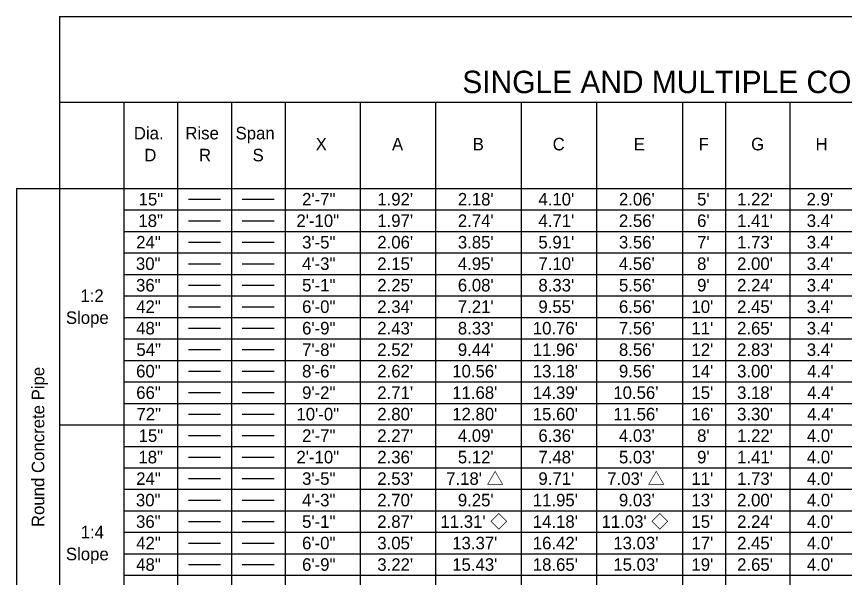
# Model space of a CAD drawing. Extents: x 1.7 to 14.6, y 0 to 8.4.
# Drawn here: x 1.7 to 6.325, y 5.298 to 8.43 of the extents above; entities that cross this region are included whole.
import ezdxf

# ---------------------------------------------------------------- set-up
doc = ezdxf.new("R2010")
doc.units = 0
doc.layers.add('Table', color=7, linetype='Continuous')

msp = doc.modelspace()

# ---------------------------------------------------------------- linework, layer by layer
at = {"layer": 'Table'}
for p, q in [((1.94, 8.43), (13.46, 8.43)), ((2.66, 7.41), (2.84, 7.41)), ((2.96, 7.41), (3.14, 7.41)), ((2.66, 7.29), (2.84, 7.29)), ((2.96, 7.29), (3.14, 7.29)), ((2.66, 7.17), (2.84, 7.17)), ((2.96, 7.17), (3.14, 7.17)), ((2.66, 7.05), (2.84, 7.05)), ((2.96, 7.05), (3.14, 7.05)), ((2.66, 6.93), (2.84, 6.93)), ((2.96, 6.93), (3.14, 6.93)), ((2.66, 6.81), (2.84, 6.81)), ((2.96, 6.81), (3.14, 6.81)), ((2.66, 6.69), (2.84, 6.69)), ((2.96, 6.69), (3.14, 6.69)), ((2.66, 6.57), (2.84, 6.57)), ((2.96, 6.57), (3.14, 6.57)), ((2.66, 6.45), (2.84, 6.45)), ((2.96, 6.45), (3.14, 6.45)), ((2.66, 6.33), (2.84, 6.33)), ((2.96, 6.33), (3.14, 6.33)), ((2.66, 6.21), (2.84, 6.21)), ((2.96, 6.21), (3.14, 6.21)), ((2.66, 6.09), (2.84, 6.09)), ((2.96, 6.09), (3.14, 6.09)), ((2.66, 5.97), (2.84, 5.97)), ((2.96, 5.97), (3.14, 5.97)), ((2.66, 5.85), (2.84, 5.85)), ((2.96, 5.85), (3.14, 5.85)), ((2.66, 5.73), (2.84, 5.73)), ((2.96, 5.73), (3.14, 5.73)), ((2.66, 5.61), (2.84, 5.61)), ((2.96, 5.61), (3.14, 5.61)), ((2.66, 5.49), (2.84, 5.49)), ((2.96, 5.49), (3.14, 5.49)), ((2.66, 5.37), (2.84, 5.37)), ((2.96, 5.37), (3.14, 5.37))]:
    msp.add_line(p, q, dxfattribs=at)
for points in [[(1.94, 8.43), (1.94, 7.83), (1.94, 7.47), (1.94, 6.15), (1.94, 4.83), (1.94, 3.51), (1.94, 2.19)], [(13.46, 7.95), (11.78, 7.95), (10.1, 7.95), (8.42, 7.95), (8.06, 7.95), (6.38, 7.95), (6.02, 7.95), (5.66, 7.95), (5.42, 7.95), (4.94, 7.95), (4.52, 7.95), (4.04, 7.95), (3.62, 7.95), (3.2, 7.95), (2.9, 7.95), (2.6, 7.95), (2.3, 7.95), (1.94, 7.95)], [(2.3, 7.95), (2.3, 7.47), (2.3, 7.35), (2.3, 7.23), (2.3, 7.11), (2.3, 6.99), (2.3, 6.87), (2.3, 6.75), (2.3, 6.63), (2.3, 6.51), (2.3, 6.39), (2.3, 6.27), (2.3, 6.15), (2.3, 6.03), (2.3, 5.91), (2.3, 5.79), (2.3, 5.67), (2.3, 5.55), (2.3, 5.43), (2.3, 5.31), (2.3, 5.19)], [(2.6, 7.95), (2.6, 7.47), (2.6, 7.35), (2.6, 7.23), (2.6, 7.11), (2.6, 6.99), (2.6, 6.87), (2.6, 6.75), (2.6, 6.63), (2.6, 6.51), (2.6, 6.39), (2.6, 6.27), (2.6, 6.15), (2.6, 6.03), (2.6, 5.91), (2.6, 5.79), (2.6, 5.67), (2.6, 5.55), (2.6, 5.43), (2.6, 5.31), (2.6, 5.19)], [(2.9, 7.95), (2.9, 7.47), (2.9, 7.35), (2.9, 7.23), (2.9, 7.11), (2.9, 6.99), (2.9, 6.87), (2.9, 6.75), (2.9, 6.63), (2.9, 6.51), (2.9, 6.39), (2.9, 6.27), (2.9, 6.15), (2.9, 6.03), (2.9, 5.91), (2.9, 5.79), (2.9, 5.67), (2.9, 5.55), (2.9, 5.43), (2.9, 5.31), (2.9, 5.19)], [(3.2, 7.95), (3.2, 7.47), (3.2, 7.35), (3.2, 7.23), (3.2, 7.11), (3.2, 6.99), (3.2, 6.87), (3.2, 6.75), (3.2, 6.63), (3.2, 6.51), (3.2, 6.39), (3.2, 6.27), (3.2, 6.15), (3.2, 6.03), (3.2, 5.91), (3.2, 5.79), (3.2, 5.67), (3.2, 5.55), (3.2, 5.43), (3.2, 5.31), (3.2, 5.19)], [(3.62, 7.95), (3.62, 7.47), (3.62, 7.35), (3.62, 7.23), (3.62, 7.11), (3.62, 6.99), (3.62, 6.87), (3.62, 6.75), (3.62, 6.63), (3.62, 6.51), (3.62, 6.39), (3.62, 6.27), (3.62, 6.15), (3.62, 6.03), (3.62, 5.91), (3.62, 5.79), (3.62, 5.67), (3.62, 5.55), (3.62, 5.43), (3.62, 5.31), (3.62, 5.19)], [(4.04, 7.95), (4.04, 7.47), (4.04, 7.35), (4.04, 7.23), (4.04, 7.11), (4.04, 6.99), (4.04, 6.87), (4.04, 6.75), (4.04, 6.63), (4.04, 6.51), (4.04, 6.39), (4.04, 6.27), (4.04, 6.15), (4.04, 6.03), (4.04, 5.91), (4.04, 5.79), (4.04, 5.67), (4.04, 5.55), (4.04, 5.43), (4.04, 5.31), (4.04, 5.19)], [(4.52, 7.95), (4.52, 7.47), (4.52, 7.35), (4.52, 7.23), (4.52, 7.11), (4.52, 6.99), (4.52, 6.87), (4.52, 6.75), (4.52, 6.63), (4.52, 6.51), (4.52, 6.39), (4.52, 6.27), (4.52, 6.15), (4.52, 6.03), (4.52, 5.91), (4.52, 5.79), (4.52, 5.67), (4.52, 5.55), (4.52, 5.43), (4.52, 5.31), (4.52, 5.19)], [(4.94, 7.95), (4.94, 7.47), (4.94, 7.35), (4.94, 7.23), (4.94, 7.11), (4.94, 6.99), (4.94, 6.87), (4.94, 6.75), (4.94, 6.63), (4.94, 6.51), (4.94, 6.39), (4.94, 6.27), (4.94, 6.15), (4.94, 6.03), (4.94, 5.91), (4.94, 5.79), (4.94, 5.67), (4.94, 5.55), (4.94, 5.43), (4.94, 5.31), (4.94, 5.19)], [(5.42, 7.95), (5.42, 7.47), (5.42, 7.35), (5.42, 7.23), (5.42, 7.11), (5.42, 6.99), (5.42, 6.87), (5.42, 6.75), (5.42, 6.63), (5.42, 6.51), (5.42, 6.39), (5.42, 6.27), (5.42, 6.15), (5.42, 6.03), (5.42, 5.91), (5.42, 5.79), (5.42, 5.67), (5.42, 5.55), (5.42, 5.43), (5.42, 5.31), (5.42, 5.19)], [(5.66, 7.95), (5.66, 7.47), (5.66, 7.35), (5.66, 7.23), (5.66, 7.11), (5.66, 6.99), (5.66, 6.87), (5.66, 6.75), (5.66, 6.63), (5.66, 6.51), (5.66, 6.39), (5.66, 6.27), (5.66, 6.15), (5.66, 6.03), (5.66, 5.91), (5.66, 5.79), (5.66, 5.67), (5.66, 5.55), (5.66, 5.43), (5.66, 5.31), (5.66, 5.19)], [(6.02, 7.95), (6.02, 7.47), (6.02, 7.35), (6.02, 7.23), (6.02, 7.11), (6.02, 6.99), (6.02, 6.87), (6.02, 6.75), (6.02, 6.63), (6.02, 6.51), (6.02, 6.39), (6.02, 6.27), (6.02, 6.15), (6.02, 6.03), (6.02, 5.91), (6.02, 5.79), (6.02, 5.67), (6.02, 5.55), (6.02, 5.43), (6.02, 5.31), (6.02, 5.19)], [(1.7, 7.47), (1.94, 7.47), (2.3, 7.47), (2.6, 7.47), (2.9, 7.47), (3.2, 7.47), (3.62, 7.47), (4.04, 7.47), (4.52, 7.47), (4.94, 7.47), (5.42, 7.47), (5.66, 7.47), (6.02, 7.47), (6.38, 7.47)], [(1.7, 7.47), (1.7, 4.83), (1.7, 2.19)], [(2.3, 7.35), (2.6, 7.35), (2.9, 7.35), (3.2, 7.35), (3.62, 7.35), (4.04, 7.35), (4.52, 7.35), (4.94, 7.35), (5.42, 7.35), (5.66, 7.35), (6.02, 7.35), (6.38, 7.35)], [(2.3, 7.23), (2.6, 7.23), (2.9, 7.23), (3.2, 7.23), (3.62, 7.23), (4.04, 7.23), (4.52, 7.23), (4.94, 7.23), (5.42, 7.23), (5.66, 7.23), (6.02, 7.23), (6.38, 7.23)], [(2.3, 7.11), (2.6, 7.11), (2.9, 7.11), (3.2, 7.11), (3.62, 7.11), (4.04, 7.11), (4.52, 7.11), (4.94, 7.11), (5.42, 7.11), (5.66, 7.11), (6.02, 7.11), (6.38, 7.11)], [(2.3, 6.99), (2.6, 6.99), (2.9, 6.99), (3.2, 6.99), (3.62, 6.99), (4.04, 6.99), (4.52, 6.99), (4.94, 6.99), (5.42, 6.99), (5.66, 6.99), (6.02, 6.99), (6.38, 6.99)], [(2.3, 6.87), (2.6, 6.87), (2.9, 6.87), (3.2, 6.87), (3.62, 6.87), (4.04, 6.87), (4.52, 6.87), (4.94, 6.87), (5.42, 6.87), (5.66, 6.87), (6.02, 6.87), (6.38, 6.87)], [(2.3, 6.75), (2.6, 6.75), (2.9, 6.75), (3.2, 6.75), (3.62, 6.75), (4.04, 6.75), (4.52, 6.75), (4.94, 6.75), (5.42, 6.75), (5.66, 6.75), (6.02, 6.75), (6.38, 6.75)], [(2.3, 6.63), (2.6, 6.63), (2.9, 6.63), (3.2, 6.63), (3.62, 6.63), (4.04, 6.63), (4.52, 6.63), (4.94, 6.63), (5.42, 6.63), (5.66, 6.63), (6.02, 6.63), (6.38, 6.63)], [(2.3, 6.51), (2.6, 6.51), (2.9, 6.51), (3.2, 6.51), (3.62, 6.51), (4.04, 6.51), (4.52, 6.51), (4.94, 6.51), (5.42, 6.51), (5.66, 6.51), (6.02, 6.51), (6.38, 6.51)], [(2.3, 6.39), (2.6, 6.39), (2.9, 6.39), (3.2, 6.39), (3.62, 6.39), (4.04, 6.39), (4.52, 6.39), (4.94, 6.39), (5.42, 6.39), (5.66, 6.39), (6.02, 6.39), (6.38, 6.39)], [(2.3, 6.27), (2.6, 6.27), (2.9, 6.27), (3.2, 6.27), (3.62, 6.27), (4.04, 6.27), (4.52, 6.27), (4.94, 6.27), (5.42, 6.27), (5.66, 6.27), (6.02, 6.27), (6.38, 6.27)], [(1.94, 6.15), (2.3, 6.15), (2.6, 6.15), (2.9, 6.15), (3.2, 6.15), (3.62, 6.15), (4.04, 6.15), (4.52, 6.15), (4.94, 6.15), (5.42, 6.15), (5.66, 6.15), (6.02, 6.15), (6.38, 6.15)], [(2.3, 6.03), (2.6, 6.03), (2.9, 6.03), (3.2, 6.03), (3.62, 6.03), (4.04, 6.03), (4.52, 6.03), (4.94, 6.03), (5.42, 6.03), (5.66, 6.03), (6.02, 6.03), (6.38, 6.03)], [(2.3, 5.91), (2.6, 5.91), (2.9, 5.91), (3.2, 5.91), (3.62, 5.91), (4.04, 5.91), (4.52, 5.91), (4.94, 5.91), (5.42, 5.91), (5.66, 5.91), (6.02, 5.91), (6.38, 5.91)], [(2.3, 5.79), (2.6, 5.79), (2.9, 5.79), (3.2, 5.79), (3.62, 5.79), (4.04, 5.79), (4.52, 5.79), (4.94, 5.79), (5.42, 5.79), (5.66, 5.79), (6.02, 5.79), (6.38, 5.79)], [(2.3, 5.67), (2.6, 5.67), (2.9, 5.67), (3.2, 5.67), (3.62, 5.67), (4.04, 5.67), (4.52, 5.67), (4.94, 5.67), (5.42, 5.67), (5.66, 5.67), (6.02, 5.67), (6.38, 5.67)], [(2.3, 5.55), (2.6, 5.55), (2.9, 5.55), (3.2, 5.55), (3.62, 5.55), (4.04, 5.55), (4.52, 5.55), (4.94, 5.55), (5.42, 5.55), (5.66, 5.55), (6.02, 5.55), (6.38, 5.55)], [(2.3, 5.43), (2.6, 5.43), (2.9, 5.43), (3.2, 5.43), (3.62, 5.43), (4.04, 5.43), (4.52, 5.43), (4.94, 5.43), (5.42, 5.43), (5.66, 5.43), (6.02, 5.43), (6.38, 5.43)], [(2.3, 5.31), (2.6, 5.31), (2.9, 5.31), (3.2, 5.31), (3.62, 5.31), (4.04, 5.31), (4.52, 5.31), (4.94, 5.31), (5.42, 5.31), (5.66, 5.31), (6.02, 5.31), (6.38, 5.31)]]:
    msp.add_lwpolyline(points, dxfattribs=at)

# ---------------------------------------------------------------- texts
for s, height, p in [('SINGLE AND MULTIPLE CONCRETE PIPE DIMENSIONS AND QUANTITIES', 0.125, (4.1904, 8.0025)), ('Dia.', 0.07, (2.3552, 7.744)), ('Rise', 0.07, (2.6431, 7.744)), ('Span', 0.07, (2.9234, 7.744)), ('X', 0.07, (3.3712, 7.6828)), ('A', 0.07, (3.7975, 7.6828)), ('B', 0.07, (4.2483, 7.6828)), ('C', 0.07, (4.6952, 7.6828)), ('E', 0.07, (5.1482, 7.6828)), ('F', 0.07, (5.5103, 7.6828)), ('G', 0.07, (5.8038, 7.6828)), ('H', 0.07, (6.1637, 7.6828)), ('D', 0.07, (2.4134, 7.6215)), ('R', 0.07, (2.7192, 7.6215)), ('S', 0.07, (3.0186, 7.6215)), ('1:2', 0.07, (2.0566, 6.8362)), ('Slope', 0.07, (1.9756, 6.7137)), ('1:4', 0.07, (2.0583, 5.5162)), ('Slope', 0.07, (1.9756, 5.3937))]:
    msp.add_text(s, height=height, dxfattribs=at).set_placement(p)
for s, rotation, p in [('15"', 0, (2.3819, 7.375)), ('2\'-7"', 0, (3.2951, 7.375)), ("1.92'", 0, (3.7154, 7.375)), ("2.18'", 0, (4.1654, 7.375)), ("4.10'", 0, (4.6154, 7.375)), ("2.06'", 0, (5.0654, 7.375)), ("5'", 0, (5.5021, 7.375)), ("1.22'", 0, (5.7254, 7.375)), ("2.9'", 0, (6.1138, 7.375)), ('18"', 0, (2.3807, 7.255)), ('2\'-10"', 0, (3.2637, 7.255)), ("1.97'", 0, (3.7154, 7.255)), ("2.74'", 0, (4.1654, 7.255)), ("4.71'", 0, (4.6154, 7.255)), ("2.56'", 0, (5.0654, 7.255)), ("6'", 0, (5.5021, 7.255)), ("1.41'", 0, (5.7254, 7.255)), ("3.4'", 0, (6.1147, 7.255)), ('24"', 0, (2.3684, 7.135)), ('3\'-5"', 0, (3.2951, 7.135)), ("2.06'", 0, (3.7154, 7.135)), ("3.85'", 0, (4.1654, 7.135)), ("5.91'", 0, (4.6154, 7.135)), ("3.56'", 0, (5.0654, 7.135)), ("7'", 0, (5.5021, 7.135)), ("1.73'", 0, (5.7254, 7.135)), ("3.4'", 0, (6.1147, 7.135)), ('30"', 0, (2.3668, 7.015)), ('4\'-3"', 0, (3.2951, 7.015)), ("2.15'", 0, (3.7154, 7.015)), ("4.95'", 0, (4.1654, 7.015)), ("7.10'", 0, (4.6154, 7.015)), ("4.56'", 0, (5.0654, 7.015)), ("8'", 0, (5.5021, 7.015)), ("2.00'", 0, (5.7254, 7.015)), ("3.4'", 0, (6.1147, 7.015)), ('36"', 0, (2.3674, 6.895)), ('5\'-1"', 0, (3.2951, 6.895)), ("2.25'", 0, (3.7154, 6.895)), ("6.08'", 0, (4.1654, 6.895)), ("8.33'", 0, (4.6154, 6.895)), ("5.56'", 0, (5.0654, 6.895)), ("9'", 0, (5.5021, 6.895)), ("2.24'", 0, (5.7254, 6.895)), ("3.4'", 0, (6.1147, 6.895)), ('42"', 0, (2.3684, 6.775)), ('6\'-0"', 0, (3.2951, 6.775)), ("2.34'", 0, (3.7154, 6.775)), ("7.21'", 0, (4.1654, 6.775)), ("9.55'", 0, (4.6154, 6.775)), ("6.56'", 0, (5.0654, 6.775)), ("10'", 0, (5.4706, 6.775)), ("2.45'", 0, (5.7254, 6.775)), ("3.4'", 0, (6.1147, 6.775)), ('48"', 0, (2.3682, 6.655)), ('6\'-9"', 0, (3.2951, 6.655)), ("2.43'", 0, (3.7154, 6.655)), ("8.33'", 0, (4.1654, 6.655)), ("10.76'", 0, (4.584, 6.655)), ("7.56'", 0, (5.0654, 6.655)), ("11'", 0, (5.4706, 6.655)), ("2.65'", 0, (5.7254, 6.655)), ("3.4'", 0, (6.1147, 6.655)), ('54"', 0, (2.3695, 6.535)), ('7\'-8"', 0, (3.2951, 6.535)), ("2.52'", 0, (3.7154, 6.535)), ("9.44'", 0, (4.1654, 6.535)), ("11.96'", 0, (4.584, 6.535)), ("8.56'", 0, (5.0654, 6.535)), ("12'", 0, (5.4706, 6.535)), ("2.83'", 0, (5.7254, 6.535)), ("3.4'", 0, (6.1147, 6.535)), ('60"', 0, (2.368, 6.415)), ('8\'-6"', 0, (3.2951, 6.415)), ("2.62'", 0, (3.7154, 6.415)), ("10.56'", 0, (4.134, 6.415)), ("13.18'", 0, (4.584, 6.415)), ("9.56'", 0, (5.0654, 6.415)), ("14'", 0, (5.4706, 6.415)), ("3.00'", 0, (5.7254, 6.415)), ("4.4'", 0, (6.1169, 6.415)), ('Round Concrete Pipe', 90, (1.855, 5.5792)), ('66"', 0, (2.3686, 6.295)), ('9\'-2"', 0, (3.2951, 6.295)), ("2.71'", 0, (3.7154, 6.295)), ("11.68'", 0, (4.134, 6.295)), ("14.39'", 0, (4.584, 6.295)), ("10.56'", 0, (5.034, 6.295)), ("15'", 0, (5.4706, 6.295)), ("3.18'", 0, (5.7254, 6.295)), ("4.4'", 0, (6.1169, 6.295)), ('72"', 0, (2.3697, 6.175)), ('10\'-0"', 0, (3.2637, 6.175)), ("2.80'", 0, (3.7154, 6.175)), ("12.80'", 0, (4.134, 6.175)), ("15.60'", 0, (4.584, 6.175)), ("11.56'", 0, (5.034, 6.175)), ("16'", 0, (5.4706, 6.175)), ("3.30'", 0, (5.7254, 6.175)), ("4.4'", 0, (6.1169, 6.175)), ('15"', 0, (2.3819, 6.055)), ('2\'-7"', 0, (3.2951, 6.055)), ("2.27'", 0, (3.7154, 6.055)), ("4.09'", 0, (4.1654, 6.055)), ("6.36'", 0, (4.6154, 6.055)), ("4.03'", 0, (5.0654, 6.055)), ("8'", 0, (5.5021, 6.055)), ("1.22'", 0, (5.7254, 6.055)), ("4.0'", 0, (6.1153, 6.055)), ('18"', 0, (2.3807, 5.935)), ('2\'-10"', 0, (3.2637, 5.935)), ("2.36'", 0, (3.7154, 5.935)), ("5.12'", 0, (4.1654, 5.935)), ("7.48'", 0, (4.6154, 5.935)), ("5.03'", 0, (5.0654, 5.935)), ("9'", 0, (5.5021, 5.935)), ("1.41'", 0, (5.7254, 5.935)), ("4.0'", 0, (6.1153, 5.935)), ('24"', 0, (2.3684, 5.815)), ('3\'-5"', 0, (3.2951, 5.815)), ("2.53'", 0, (3.7154, 5.815)), ("7.18' △", 0, (4.1, 5.815)), ("9.71'", 0, (4.6154, 5.815)), ("7.03' △", 0, (5, 5.815)), ("11'", 0, (5.4706, 5.815)), ("1.73'", 0, (5.7254, 5.815)), ("4.0'", 0, (6.1153, 5.815)), ('30"', 0, (2.3668, 5.695)), ('4\'-3"', 0, (3.2951, 5.695)), ("2.70'", 0, (3.7154, 5.695)), ("9.25'", 0, (4.1654, 5.695)), ("11.95'", 0, (4.584, 5.695)), ("9.03'", 0, (5.0654, 5.695)), ("13'", 0, (5.4706, 5.695)), ("2.00'", 0, (5.7254, 5.695)), ("4.0'", 0, (6.1153, 5.695)), ('36"', 0, (2.3674, 5.575)), ('5\'-1"', 0, (3.2951, 5.575)), ("2.87'", 0, (3.7154, 5.575)), ("11.31' ◇", 0, (4.0683, 5.575)), ("14.18'", 0, (4.584, 5.575)), ("11.03' ◇", 0, (4.9683, 5.575)), ("15'", 0, (5.4706, 5.575)), ("2.24'", 0, (5.7254, 5.575)), ("4.0'", 0, (6.1153, 5.575)), ('42"', 0, (2.3684, 5.455)), ('6\'-0"', 0, (3.2951, 5.455)), ("3.05'", 0, (3.7154, 5.455)), ("13.37'", 0, (4.134, 5.455)), ("16.42'", 0, (4.584, 5.455)), ("13.03'", 0, (5.034, 5.455)), ("17'", 0, (5.4706, 5.455)), ("2.45'", 0, (5.7254, 5.455)), ("4.0'", 0, (6.1153, 5.455)), ('48"', 0, (2.3682, 5.335)), ('6\'-9"', 0, (3.2951, 5.335)), ("3.22'", 0, (3.7154, 5.335)), ("15.43'", 0, (4.134, 5.335)), ("18.65'", 0, (4.584, 5.335)), ("15.03'", 0, (5.034, 5.335)), ("19'", 0, (5.4706, 5.335)), ("2.65'", 0, (5.7254, 5.335)), ("4.0'", 0, (6.1153, 5.335))]:
    msp.add_text(s, height=0.07, rotation=rotation, dxfattribs=at).set_placement(p)

doc.saveas('drawing.dxf')
